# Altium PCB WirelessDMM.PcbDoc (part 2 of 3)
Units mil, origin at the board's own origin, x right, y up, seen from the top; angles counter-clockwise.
Board outline 6000 x 520 mil, 6 copper layers (Layer 1 - Top Layer, Layer 2 - GND, Layer 3 - Signal, Layer 4 - PWR, Layer 5 - GND, Layer 6 - Bottom Layer), stack 63.468 mil thick; 198 components, 117 nets, 636 pads, 272 vias.
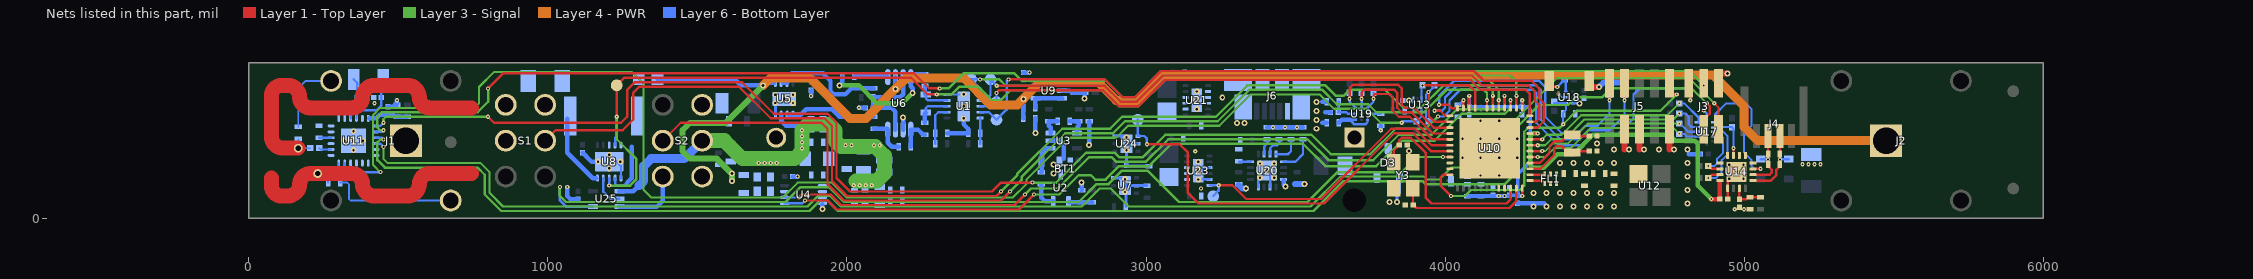
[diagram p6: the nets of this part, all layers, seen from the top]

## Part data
BT1: "HOLDER BATTERY AAA, TH"
C1: "CAP, CERM, 0.1 µF, 16 V, +/- 5%, X7R, 0402"
C2 C8 C9 C21 C25 C26 C29 C30 C31 C32 C33 C35 C38 C46 C51 C52 C71: "CAP, CERM, 0.1 µF, 10 V, +/- 10%, X5R, 0201"
C3 C4 C24 C28 C36 C47 C55 C58 C65 C66 C69 C72: "CAP, CERM, 1 µF, 10 V, +/- 10%, X5R, 0402"
C5 C27 C39 C68: "CAP, CERM, 1 µF, 6.3 V, +/- 20%, X5R, 0402"
C6: "CAP, CERM, 22 µF, 6.3 V, +/- 20%, X5R, 0402"
C7: "CAP, CERM, 4.7 µF, 35 V, +/- 10%, X5R, 0603"
C10 C11: "CAP, CERM, 1200 pF, 50 V, +/- 5%, C0G/NP0, 0402"
C12: "CAP, CERM, 0.1 µF, 50 V, +/- 5%, X7R, 0603"
C13: "CAP, CERM, 10 pF, 50 V, +/- 1%, C0G/NP0, 0603"
C14: "CAP, CERM, 0.01 µF, 100 V, +/- 1%, C0G/NP0, 0805"
C15: "CAP, CERM, 330 pF, 50 V, +/- 1%, C0G/NP0, 0402"
C16: "CAP, CERM, 470 pF, 50 V, +/- 1%, C0G/NP0, 0805"
C17: "CAP, CERM, 150 pF, 50 V, +/- 5%, C0G/NP0, 0402"
C18 C19: library part Capacitor, "Cap, 0402 footprint placeholder"
C20: "CAP, CERM, 2200 pF, 50 V, +/- 5%, C0G/NP0, 0603"
C22: "CAP, CERM, 100 pF, 100 V, +/- 1%, C0G/NP0, 0603"
C23: "CAP, CERM, 0.022 µF, 100 V, +/- 10%, X7R, 0603"
C34 C56 C57: "CAP, CERM, 4.7 µF, 10 V, +/- 10%, X5R, 0402"
C37 C49 C50: "CAP, CERM, 39 pF, 50 V, +/- 5%, C0G/NP0, 0402"
C40 C41: "CAP, CERM, 22 pF, 25 V, +/- 5%, C0G/NP0, AEC-Q200 Grade 1, 0201"
C42 C43 C44 C45: "CAP, CERM, 12 pF, 50 V, +/- 5%, C0G/NP0, 0201"
C48 C53: "CAP, CERM, 0.47 µF, 6.3 V, +/- 10%, X5R, 0201"
C54: "CAP, CERM, 2.2 µF, 16 V, +/- 10%, X5R, 0402"
C59 C62 C64 C67: "CAP, CERM, 10 µF, 10 V, +/- 20%, X5R, 0402"
C63: "CAP, CERM, 100 µF, 10 V, +/- 20%, X5R, 1206_190"
C70: "CAP, CERM, 2.2 µF, 6.3 V, +/- 10%, X5R, 0402"
D1 D2: "Diode, Schottky, 35 V, 0.1 A, SOD-523F"
D3: "MOSFET, P-CH, -20 V, -3.7 A, SOT-23"
F1: "Fuse, Resettable, 0.2 A, 24 VDC, SMD"
FID1 FID2 FID3 FID4 FID5 FID6: "Fiducial mark.  There is nothing to buy or mount."
FL1: "Filter, BandPass, 2.45GHz, SMD"
J1: "MAH561 Connector, XELW-4, Red, THD"
J2: "MAH561 Connector, XELW-4, Black, THD"
J3: "Header, 1.27 mm, 3x2, Au, SMT"
J4: "CONN FFC BOTTOM 4POS 1.00MM R/A"
J5: "Header, 1.27mm, 5x2, Gold, SMT"
J6: "Connector, Receptacle, Micro-USB Type B, R/A, Bottom Mount SMT"
L1 L2: "Inductor, Multilayer, Ferrite, 2.2 µH, 0.21 A, 0.15 ohm, SMD"
L3: "Ferrite Bead, 1500 ohm @ 100 MHz, 0.5 A, 0603"
Logo2: library part Pb-Free
Logo3: library part FCC_disclaimer, "FCC_disclaimer"
R1 R24: "RES, 13.3 k, 1%, 0.063 W, 0402"
R2: "RES, 8.2, 5%, 0.063 W, 0402"
R3: "RES, 10.0 k, 1%, 0.063 W, 0402"
R4 R14: "RES, 3.01 k, 1%, 0.063 W, 0402"
R5 R15: "RES, 52.3, 1%, 0.063 W, 0402"
R6: "RES, 9.76 k, 1%, 0.063 W, 0402"
R7: "RES, 100 k, 0.1%, 0.063 W, 0402"
R8: "RES, 1.00 M, 1%, 0.063 W, 0402"
R9: "RES, 100 M, 5%, 0.1 W, 0603"
R10: "RES, 10.0, 1%, 0.063 W, 0402"
R11 R13 R28 R29 R30 R31 R32 R51 R52 R53 R54 R56 R57 R58: "RES, 0, 5%, 0.063 W, 0402"
R12: "RES, 10.2 k, 1%, 0.063 W, 0402"
R16: "RES, 10.0 M, 1%, 0.3 W, 1206"
R17: "RES, 499 k, 1%, 0.063 W, 0402"
R19 R23: "RES, 133 k, 1%, 0.063 W, 0402"
R20: "RES, 95.3, 1%, 1 W, 2512"
R21: "RES, 11.3 k, 1%, 0.063 W, 0402"
R25: "RES, 0.5, 1%, 0.1 W, 0603"
R26 R27: "RES, 909, 1%, 0.05 W, 0201"
R33 R35 R36 R37 R38 R59 R60 R61 R62 R63 R64: "RES, 47.0 k, 1%, 0.05 W, AEC-Q200 Grade 0, 0201"
R34: "RES, 200 k, 1%, 0.063 W, 0402"
R39: "RES, 100 k, 1%, 0.05 W, 0201"
R40: "RES, 1.00 k, 1%, 0.05 W, 0201"
R41 R42 R43: "RES, 10.0 k, 1%, 0.05 W, 0201"
R44: "RES, 10.0 k, 1%, 0.1 W, 0402"
R45: "RES, 0.01, 1%, 0.25 W, 0805"
R46: "RES, 10 k, 5%, 0.063 W, 0402"
R47: "RES, 1.15 k, 1%, 0.063 W, 0402"
R48: "RES, 9.31 k, 1%, 0.063 W, 0402"
R49: "RES, 5.76 k, 1%, 0.063 W, 0402"
R50: "RES, 30.1 k, 1%, 0.063 W, 0402"
R55: "RES, 1.0 k, 5%, 0.063 W, 0402"
R65: library part RK73H1HTTC4702F, "RES, 47.0 k, 1%, 0.05 W, AEC-Q200 Grade 0, 0201"
S1 S2: "Switch, Slide, DPDT, On-On, 0.5 A, 125 V, TH"
S3: "SWITCH TACTILE SPST-NO 0.05A 12V"
TP1 TP2 TP3 TP4 TP6 TP9 TP10: library part TP_SM_1MM, "1mm Test Point, SMT"
TP7 TP8: library part TP_H0.45P0.75, "Testpoint"
U1: "18-Bit, 400-kSPS, Serial Interface, microPower, Miniature, True-Differential Input, SAR Analog-to-Digital Converter, DRC0010D"
U2: "30 ppm / degC Drift, 3.9 uA Voltage Reference, -40 to 125 degC, 3-pin SC70 (DCK), Green (RoHS & no Sb/Br)"
U3: "1-MHz, Micro-Power, Low-Noise, RRIO,1.8-V CMOS OPERATIONAL AMPLIFIER Precision Value Line Series, DCK0005A"
U4: "1-Ohm SP3T ANALOG SWITCH 5-V/3.3-V SINGLE-CHANNEL 3:1 MULTIPLEXER/DEMULTIPLEXER, DCU0008A"
U5: "1-MHz, Micro-Power, Low-Noise, RRIO,1.8-V CMOS OPERATIONAL AMPLIFIER Precision Value Line Series, DRG0008A"
U6: "Ultra Low Power, Rail-to-Rail Output, Fully-Differential Amplifier, DGK0008A"
U7: "Single Output LDO, 150 mA, Fixed 3 V Output, 2.2 to 5.5 V Input, with 0.5 uA Quiescent Current, 6-pin SON (DRV), -40 to 125 degC, Green (RoHS & no Sb/Br)"
U8: "0.3-ohm 2-Channel SPDT Bidirectional Analog Switch Dual-Channel 2:1 Multiplexer and Demultiplexer, DRC0010J"
U9: "17 uA, MicroPower, Precision, Zero Drift CMOS Operational Amplifier, 1.8 to 5.5 V, -40 to 125 degC, 5-pin SOT23 (DCK0005A), Green (RoHS & no Sb/Br)"
U10: "Ultra low-power ARM Cortex M3 2.4 GHz Radio MCU, Bluetooth Low Energy, RGZ0048A"
U11: "Mixed-Signal Microcontrollers, RGE0024G"
U12: "2.4GHz Antenna, 50 Ohms, SMD"
U13: "2-Channel Bidirectional Multi-Voltage Level Translator for Open-Drain & Push-Pull Application, DQE0008A"
U14: "DYNAMIC NFC INTERFACE TRANSPONDER, RGT0016C"
U15 U16: "ESD in 0402 Package with 10 pF Capacitance and 6 V Breakdown, 1 Channel, -40 to +125 degC, 2-pin X2SON (DPY), Green (RoHS & no Sb/Br)"
U17: "4-Bits Bidirectional Multi-Voltage Level Translator for Open-Drain and PushPull Application, RUT0012A"
U18: "Low-Power, Push-Button Controllers With Configurable Delay, DRY0006A"
U19: "System-Side Impedance Track Fuel Gauge, YZF0009-C01"
U20: "USB Friendly 0.5 A Li+ Charger with Dynamic Power Management, 10.5 V OVP, 4.3 V, -40 to 85 degC, 16-pin QFN (RGT), Green (RoHS & no Sb/Br)"
U21 U23: "360nA IQ Step Down Converter for Low Power Applications, DSS0012A"
U24: "Single Output LDO, 150 mA, Fixed 2.7 V Output, 2.2 to 5.5 V Input, with 0.5 uA Quiescent Current, 6-pin SON (DRV), -40 to 85 degC, Green (RoHS & no Sb/Br)"
U25: "0.9-Ohm SPST ANALOG SWITCH, DCK0005A"
Y1: "Crystal, 32.768 KHz, 12.5 pF, SMD"
Y2: "Crystal, 32.768kHz, 12.5pF, SMD"
Y3: "Crystal, 24 MHz, 9 pF, SMD"
ZZ2 ZZ3 ZZ4: library part AssemblyNote

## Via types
v1: diameter 14, hole 6, Layer 1 - Top Layer to Layer 6 - Bottom Layer, tented both sides, 136 vias
v2: diameter 20, hole 10, Layer 1 - Top Layer to Layer 6 - Bottom Layer, tented both sides, 85 vias
v3: diameter 19.68, hole 7.87, Layer 1 - Top Layer to Layer 6 - Bottom Layer, tented both sides, 35 vias
v4: diameter 19.68, hole 7.87, Layer 1 - Top Layer to Layer 6 - Bottom Layer, 14 vias
v5: diameter 10, hole 6, Layer 1 - Top Layer to Layer 6 - Bottom Layer, tented both sides, 2 vias

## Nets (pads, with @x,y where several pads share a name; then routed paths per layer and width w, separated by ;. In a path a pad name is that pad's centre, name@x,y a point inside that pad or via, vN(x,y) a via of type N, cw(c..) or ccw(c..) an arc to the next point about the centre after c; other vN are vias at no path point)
ADS8881_CNVST: TP4.1 U1.6 U10.14 | length 2050.7
  Layer 1 - Top Layer w8: U10.14@4238.58,368.86 v1(4238.58,410)
  Layer 3 - Signal w8: v1(2445.12,464.88) 2510.12,464.88 2531,444 2861.79,444 2915.79,390 2968.79,390 3056.79,478 4217,478 4238.58,456.42 v1(4238.58,410)
  Layer 6 - Bottom Layer w8: U1.6@2445.12,414.37 2445.12,434.88 TP4.1@2415,465 2445,465 v1(2445.12,464.88)
ADS8881_MISO: TP3.1 U1.7 U10.11 | length 2136
  Layer 1 - Top Layer w8: v1(2501,444) 2861.79,444 2915.79,390 2968.79,390 3056.79,478 4090.79,478 4123.79,445 4280,445 4300,425 4300,395 4315,380 4315,335 4303.58,323.58 U10.11@4283.86,323.58
  Layer 6 - Bottom Layer w8: U1.7@2445.12,394.68 2461.68,394.68 2480,413 TP3.1@2480,465 v1(2501,444)
ADS8881_MOSI: TP1.1 U1.9 U10.10 | length 2248.4
  Layer 1 - Top Layer w8: v1(2540,465) 2862,465 2922,405 2962.57,405 3050.57,493 4097,493 4130,460 4290,460 4315,435 4315,401.21 4330,386.21 4330,325 4308.9,303.9 U10.10@4283.86,303.9
  Layer 6 - Bottom Layer w8: U1.9@2445.12,355.31 2474.68,355.31 TP1.1@2500,330 2534,364 2534,459 v1(2540,465)
ADS8881_SCLK: TP2.1 U1.8 U10.12 | length 2030.4
  Layer 1 - Top Layer w8: v1(2500,420) 2509,429 2855.57,429 2909.57,375 2975,375 3063,463 4084.57,463 4117.57,430 4270,430 4283.86,416.14 U10.12@4283.86,343.27
  Layer 6 - Bottom Layer w8: U1.8@2445.12,375 2484,375 2498,389 TP2.1@2500,389 v1(2500,420)
AFE_IRNG-SEL: TP6.1 U8.4 U8.8 U10.17 | length 3721
  Layer 1 - Top Layer w8: v1(1230,340) TP6.1@1230,445 1255,470 2215,470 2270,415 v1(2300,415) ; U10.17@4179.53,368.86 v1(4179.53,395)
  Layer 3 - Signal w8: v1(1205,110) 1275,110 1295,130 1295,200 1230,265 v1(1230,340) ; v1(2300,415) 2350,415 2375,440 2440,440 2484,396 2515,396 2548,429 2855.57,429 2909.57,375 2975,375 3063,463 4147,463 4179.53,430.47 v1(4179.53,395)
  Layer 6 - Bottom Layer w8: v1(1205,110) U8.8@1205,134.88 ; U8.4@1224.68,245.12 1224.68,269.68 1230,275 v1(1230,340)
AFE_RIN-SEL: S2.5 U10.19 | length 3273.5
  Layer 1 - Top Layer w8: S2.5@1384.06,260 1444.06,320 1915,320 1935,300 1935,115 1990,60 2515,60 v1(2545,90) ; U10.19@4140.16,368.86 v1(4140.16,395)
  Layer 3 - Signal w8: v1(2545,90) 2585,130 2585,140 2730,285 2890,285 2930,325 3240,325 3345,430 3590,430 3638,382 3743,382 3770,355 3930,355 4005,430 4130,430 4140.16,419.84 v1(4140.16,395)
AFE_VI-SEL: S1.2 U10.18 | length 3855.1
  Layer 1 - Top Layer w8: S1.2@990.94,260 1025.94,295 1250,295 1285,330 1285,420 1305,440 1640,440 1745,335 1925,335 1950,310 1950,125 2000,75 2500,75 v1(2515,90) ; U10.18@4159.84,368.86 v1(4159.84,410)
  Layer 3 - Signal w8: v1(2515,90) 2570,145 2570,150 2720,300 2880,300 2920,340 3233.79,340 3338.79,445 3600,445 3635,410 3660,410 3680,430 3800,430 3860,370 3920,370 3995,445 4140,445 4159.84,425.16 v1(4159.84,410)
AFE_VRNG-SEL0: U4.6 U10.16 | length 2709.5
  Layer 1 - Top Layer w8: v1(1840,70.16) 1849.84,80 1945,80 1980,45 2560,45 v1(2595,80) ; U10.16@4199.21,368.86 v1(4199.21,410)
  Layer 3 - Signal w8: v1(2595,80) 2615,100 2705,100 2810,205 2885,205 2900,190 3000,190 3075,265 3540,265 3610,195 3760,195 3845,280 3955,280 4040,365 4190,365 4199.21,374.21 v1(4199.21,410)
  Layer 6 - Bottom Layer w8: U4.6@1792.01,70.16 v1(1840,70.16)
AFE_VRNG-SEL1: U4.5 U10.15 | length 2710.5
  Layer 1 - Top Layer w8: v1(1860,60) 1935,60 1965,30 2575,30 v1(2625,80) ; U10.15@4218.9,368.86 v1(4218.9,395)
  Layer 3 - Signal w8: v1(2625,80) 2710,80 2775,145 2815,145 2830.1,129.9 2864.9,129.9 2910,175 3010,175 3085,250 3525,250 3600,175 3770,175 3855,260 3965,260 4055,350 4200,350 4218.9,368.9 v1(4218.9,395)
  Layer 6 - Bottom Layer w8: U4.5@1792.01,50.47 1850.47,50.47 v1(1860,60)
AINM: C20.1 R15.2 U1.4 | length 118.7
  Layer 6 - Bottom Layer w8: R15.2@2260,442 R15.2@2261,443 ; C20.1@2265,415 2265,400 2270.32,394.68 U1.4@2334.88,394.68
  Layer 6 - Bottom Layer w15: R15.2@2261,443 2261,417 C20.1@2264,414
AINP: C20.2 R5.2 U1.3 | length 124
  Layer 6 - Bottom Layer w8: C20.2@2264,354 2264,369 2270,375 U1.3@2334.88,375
  Layer 6 - Bottom Layer w15: R5.2@2260,320 2260,350 C20.2@2264,354
BQ27426_GPIO: R43.1 U10.29 U19.A1 | length 416.1
  Layer 1 - Top Layer w8: v1(3760.85,400) 3760.85,410.85 3766,416 3814,416 3825,405 3825,360 3845,340 3882,340 3957.47,264.53 U10.29@4016.14,264.53
  Layer 6 - Bottom Layer w8: U19.A1@3740.53,369.69 3760.85,390 R43.1@3760.85,420.04
BQ27426_SCL: R41.1 U10.27 U19.A3 | length 526
  Layer 1 - Top Layer w8: v1(3680.85,400) 3680.85,435.85 3692,447 3843,447 3855,435 3855,380 3865,370 3896,370 3962.1,303.9 U10.27@4016.14,303.9
  Layer 6 - Bottom Layer w8: R41.1@3680.85,420.04 3680.85,390 U19.A3@3701.16,369.69
BQ27426_SDA: R42.1 U10.28 U19.A2 | length 461.4
  Layer 1 - Top Layer w8: v1(3720.85,400) 3720.85,421.85 3730,431 3829,431 3840,420 3840,370 3855,355 3888,355 3958.79,284.21 U10.28@4016.14,284.21
  Layer 6 - Bottom Layer w8: U19.A2@3720.85,369.69 v1(3720.85,400) R42.1@3720.85,420.04
CAP02: R26.1 R28.2 TP7.1 | length 908.4
  Layer 1 - Top Layer w50: 75,135 75,110 ccw(c110,110) 110,75 130,75 ccw(c130,115) 170,115 cw(c205,115) 205,150 TP7.1@230,150 345,150 cw(c345,115) 380,115 ccw(c420,115) 420,75 530,75 ccw(c530,115) 570,115 cw(c605,115) 605,150 745,150
  Layer 6 - Bottom Layer w6: TP7.1@230,150 R26.1@270.04,150 ; R28.2@265,120 R26.1@265,144.96
CAP12: R27.1 R31.2 TP8.1 | length 1136.3
  Layer 1 - Top Layer w50: TP8.1@165,235 115,235 cw(c115,275) 75,275 75,410 cw(c110,410) 110,445 130,445 cw(c130,405) 170,405 ccw(c205,405) 205,370 345,370 ccw(c345,405) 380,405 cw(c420,405) 420,445 530,445 cw(c530,405) 570,405 ccw(c605,405) 605,370 745,370
  Layer 6 - Bottom Layer w6: R31.2@165,265 TP8.1@165,235 R27.1@205.04,235
CC2640_HFXN: C45.1 U10.46 Y3.3 | length 678.6
  Layer 1 - Top Layer w8: Y3.3@3828.5,188.31 3828.5,226.5 C45.1@3847.01,245 3847.01,262.01 3855,270 3885,270 3935,220 3935,70 3955,50 4205,50 4218.9,63.9 U10.46@4218.9,101.14
CC2640_HFXP: C44.1 U10.47 Y3.1 | length 460.2
  Layer 1 - Top Layer w8: Y3.1@3896.48,101.69 3892.99,98.21 C44.1@3892.99,45 3895,45 3905,35 4215,35 4238.58,58.58 U10.47@4238.58,101.14
CC2640_NRESET: C70.1 J5.10 R40.1 U10.35 U18.1 | length 1246.7
  Layer 1 - Top Layer w8: U10.35@4016.14,146.42 3993.58,146.42 3985,137.83 3985,110 v1(4020,75) ; J5.10@4755,415 v1(4775,415)
  Layer 3 - Signal w8: v1(4020,75) 4066.81,75 4086.81,95 4250,95 4265,110 4265,290 4278.9,303.9 4383.9,303.9 v1(4395,315) 4440,360 4720,360 v1(4775,415)
  Layer 6 - Bottom Layer w7: R40.1@4365,385.04 4365.28,385.31 U18.1@4404.17,385.31 4404.17,362.17 4395,353 C70.1@4395,350 v1(4395,315)
CC2650_LFXI: C42.2 U10.4 Y2.2 | length 252.3
  Layer 1 - Top Layer w8: U10.4@4283.86,185.79 4316.79,185.79 4349.44,218.44 4349.44,241.44 4365.56,257.56 4389.56,257.56 4411.53,279.53 Y2.2@4425,279.53 4429.53,275 C42.2@4482.01,275
CC2650_LFXO: C43.1 U10.3 Y2.1 | length 253.9
  Layer 1 - Top Layer w8: U10.3@4283.86,166.1 4319.1,166.1 4365,212 4365,235 4372,242 4389,242 4410.53,220.47 Y2.1@4425,220.47 4429.53,225 C43.1@4482.01,225
COM: C18.2 C19.2 C27.1 J2.1 R9.2 R25.1 R55.1 U4.7 U5.5 U6.2 | length 5267.7
  Layer 3 - Signal w20: v2(1615,125) v2(1615,150) 1565,200 1475,200 1450,225 1450,295 1475,320 1595,320 v2(1720,445)
  Layer 4 - PWR w30: v2(1720,445) 1745,470 1875,470 2010,335 2064.2,335 v2(2162.2,433) 2199.2,470 2390,470 2480,380 2570,380 v2(2590,400) 2645,455 2840,455 2900,395 2970,395 3055,480 4895,480 5000,375 5000,305 5045,260 J2.1@5474.61,260
  Layer 6 - Bottom Layer w15: R25.1@1366.5,465 1625,465 1645,445 v2(1720,445) 1728.15,453.15 U5.5@1757.15,453.15 ; v2(2162.2,433) U6.2@2162.2,472.6 ; C27.1@2590,334.7 R55.1@2590,370 v2(2590,400)
CURR_IN: F1.1 S1.4
DMM_IN: J1.1 S1.5
GND: BT1.2 C2.1 C3.1 C4.1 C5.2 C6.2 C7.2 C8.1 C9.1 C21.1 C24.2 C25.1 C26.1 C27.2 C28.2 C29.2 C30.2 C31.2 C32.2 C33.2 C34.2 C35.2 C36.2 C37.2 C38.1 C39.2 C40.2 C41.2 C42.1 C43.2 C44.2 C45.2 C46.2 C47.2 C48.2 C51.1 C52.2 C53.2 C54.2 C55.1 C56.2 C57.2 C58.2 C59.2 C62.2 C63.2 C64.2 C65.2 C66.2 C67.2 C68.2 C69.2 C70.2 C71.1 C72.2 D3.1 FL1.2 FL1.5 FL1.6 J3.6 J5.3 J5.5 J5.9 J6.5 J6.6 J6.7 J6.8 J6.9 J6.10 J6.11 R24.1 R29.1 R44.2 R46.1 R47.1 R48.1 R49.1 R50.1 S1.1 S2.6 S3.1 U1.5 U1.11 U2.3 U3.2 U4.4 U5.4 U5.9 U6.6 U7.3 U7.5 U7.7@2930,110 U8.6 U8.11 U9.2 U10.33 U10.34 U10.49 U11.5 U11.6 U11.7 U11.8 U11.9 U11.10 U11.13 U11.15 U11.17 U11.18 U11.19 U11.20 U11.23 U11.25 U13.1 U14.4 U14.5 U14.6 U14.8 U14.9 U14.13 U14.17@4974.47,156.09 U15.2 U16.2 U17.6 U18.2 U18.6 U19.B2 U20.4 U20.6 U20.8 U20.17@3405,160 U21.3 U21.4 U21.8 U21.9 U21.10 U21.13@3170,395 U23.3 U23.4 U23.9 U23.11 U23.13@3175,160 U24.3 U24.5 U24.7@2935,250 U25.3 Y3.2 Y3.4 | length 2786.8
  Layer 1 - Top Layer w8: C48.2@4944.99,65 4944.99,124.99 U14.17@4974.47,154.47
  Layer 1 - Top Layer w20: S3.1@4481.93,460 4486.93,455 4486.93,440 v2(4515,440) ; 4600,230 J5.3@4600,298.23 ; 4650,230 J5.5@4650,298.23 ; 4750,230 J5.9@4750,298.23 ; J3.6@4920,485 v2(4945,485)
  Layer 6 - Bottom Layer w6: v1(4379,417) 4391,405 U18.2@4403.19,405
  Layer 6 - Bottom Layer w7: U18.6@4426.81,385.31 4449.69,385.31 v2(4450,385) ; v1(4865,361) 4875,351 U17.6@4875,323.46
  Layer 6 - Bottom Layer w8: U8.11@1225,195 1244.37,175.63 U8.6@1244.37,134.88 ; U1.5@2334.88,414.37 2388.03,414.37 U1.11@2390,412.4 ; U23.13@3175.26,130.47 U23.11@3212.4,130.47 U23.11@3212.66,130.47 ; U23.13@3175.26,160 3185.1,169.84 U23.9@3212.4,169.84 U23.9@3212.66,169.84 ; U20.8@3375.47,104.88 3375.47,130.47 v3(3381.38,136.38) v3(3405,160) 3414.84,150.16 U20.6@3414.84,104.88
  Layer 6 - Bottom Layer w10: U5.4@1760.47,346.85 v4(1760.47,386.22) ; U7.3@2891.61,135.59 U7.7@2919.41,135.59 ; U24.3@2896.61,275.59 U24.7@2934.41,275.59 ; v4(2930,88.35) 2933,85.35 C24.2@2933,40 ; U7.7@2930,110 U7.5@2968.39,110 C72.2@3003,110 ; C65.2@2934.74,180 U24.7@2934.74,228.09 ; U24.7@2935,250 U24.5@2973.39,250 ; C65.2@2939.74,175 C66.2@3010,175 ; v2(3840,55) 3840,78 3847.4,85.4 D3.1@3847.4,138.76
  Layer 6 - Bottom Layer w15: C35.2@465,372.99 482.99,372.99 490,380 C34.2@495,380 v1(495,395) ; v1(1065,105) 1065,75 1074.99,65.01 C71.1@1101,65.01 ; C26.1@1116,220.01 1146.01,190 v4(1167.6,190) ; U25.3@1239.29,39.72 1364.72,39.72 1384.06,59.06 S2.6@1384.06,139.92 ; C8.1@1817.99,140 v1(1835,140) ; v1(1879.99,409.01) C21.1@1880,429.01 ; v2(1917.99,32.01) U4.4@1917.99,48 ; v1(2040,370) C9.1@2062.01,370 ; U6.6@2187.8,297.4 v2(2187.8,337) ; C3.1@2335,285 C4.1@2405,285 2405,300 2390,315 U1.11@2390,337.6 ; C25.1@2590,487.99 v1(2610,487.99) ; v2(2630,285) C27.2@2630,334.7 ; U3.2@2680.71,260 2710,260 2725,245 2725,200 ; U9.2@2719.29,427.22 2745.78,427.22 2753,420 C68.2@2760,420 R24.1@2795,420 v2(2795,401) ; C5.2@2785,95 v2(2785,120) ; v2(2810,245) C6.2@2810,325 ; R50.1@3405,305 v1(3425,305) R47.1@3445,305 v1(3465,305) R49.1@3485,305 v1(3505,305) R46.1@3525,305 ; U20.4@3460.12,127 3460.12,112.88 v2(3466,107) ; 3590,320 C58.2@3605,320 ; 3590,390 C54.2@3605,390 ; 3600,355 C53.2@3617.01,355 ; v1(3785,295) R44.2@3785,310 ; C32.2@4243,51.01 4330.99,51.01 ; 4815,215 C51.1@4854.01,215
  Layer 6 - Bottom Layer w20: C56.2@3310,112 3322,100 v2(3335,100) ; C57.2@3499,115 C57.2@3505,115 v2(3530,115) ; v2(4515,440) 4529.69,454.69 U16.2@4600,454.69
  other v1: 4968.94,31.09 5000,31.09 3184,100 5195,181.3 5215,181.3 5235,181.3 5255,181.3 3165,225 420,385
  other v2: 4295,40 4340,40 4385,40 4430,40 4475,40 4520,40 4565,40 4810,50 3815,55 4295,85 4340,85 4385,85 4430,85 4475,85 4520,85 4565,85 4810,95 4810,140 2690,150 2690,180 4385,185 4430,185 4475,185 4520,185 4565,185 4810,185 3880,226 4565,230 4615,230 4665,230 4715,230 4765,230 4810,230 4508,250 3570,300 3305,320 3330,320 3570,330 3570,360 3570,390 3879,395 3255,405
  other v3: 3175,130.47 4950.85,132.47 4998.09,132.47 3428.62,136.38 4118.37,143.46 4181.63,143.46 4974.47,156.09 3175,160 4950.85,179.71 4998.09,179.71 3381.38,183.62 3428.62,183.62 3175,189.53 4058.46,203.37 4118.37,203.37 4181.63,203.37 4241.54,203.37 2935,228.35 350,228.5 318.5,260 350,260 381.5,260 4058.46,266.63 4118.37,266.63 4181.63,266.63 4241.54,266.63 2935,271.65 350,291.5 4118.37,326.54 4181.63,326.54 3170,365.47 3170,395 3170,424.53
  other v4: 2930,131.65 1205,167.36 1242.4,190 1205,212.64 2390,334.65 2390,375 1819.53,386.22 1790,400 1760.47,413.78 1819.53,413.78 2390,415.35
  other v5: 3720.85,350
I-SEL: U10.32 U25.4 | length 3369.3
  Layer 1 - Top Layer w8: v1(3993,205.47) U10.32@4016.14,205.47
  Layer 3 - Signal w8: v1(1040,105) 1040,75 1060,55 1795,55 1845,105 1940,105 1990,55 2775,55 2835,115 2875,115 2920,160 3005,160 3110,55 3540,55 3640,155 3855,155 3905.47,205.47 v1(3993,205.47)
  Layer 6 - Bottom Layer w8: v1(1040,105) 1040,60 1060.28,39.72 U25.4@1150.71,39.72
IN_P: C10.1 C11.1 C12.1 C13.1 C14.1 C15.1 C16.1 C17.1 C18.1 C19.1 R10.1 R11.1 R12.1 R13.1 S2.2 U5.3 U25.1 | length 1431.5
  Layer 3 - Signal w50: S2.2@1515.94,260 1590,260 1650,200 1825,200 1850,225 v1(1850,235) v1(1850,255) v1(1850,275) v1(1850,295) 1870,315 1940,315 1960,295 1960,260 1980,240 2095,240 2125,210 2125,150 2100,125 2030,125
  Layer 6 - Bottom Layer w15: U25.1@1239.29,90.91 1285.91,90.91 1305,110 ; U5.3@1780.16,346.85 1780.16,325.84 1796,310 1835,310 v1(1850,295)
  Layer 6 - Bottom Layer w30: 1305,110 1320,125 1320,175 1345,200 1455.94,200 S2.2@1515.94,260
  other v1: 2023,111 2043,111 2063,111 2083,111 1705,185 1725,185 1745,185 1765,185 1995,245 2015,245 2090,245 2110,245
JTAG_TCK: J5.4 U10.25 U16.1 | length 1042.1
  Layer 1 - Top Layer w8: v1(3965,360) 3984,360 4000.73,343.27 U10.25@4016.14,343.27 ; v1(4600,395) J5.4@4600,451.77
  Layer 6 - Bottom Layer w8: v1(3965,360) 3990,360 4000,370 4000,405 4040,445 4305,445 4320,430 4320,330 4385,265 4450,265 4480,295 4550,295 4600,345 v1(4600,395) U16.1@4600,415.32
JTAG_TMS: J5.2 U10.24 U15.1 | length 967.1
  Layer 1 - Top Layer w8: v1(3980,380) 4010.59,380 4021.73,368.86 U10.24@4041.73,368.86 ; v1(4550,395) J5.2@4550,451.77
  Layer 6 - Bottom Layer w8: v1(3980,380) 3980,410 4030,460 4315,460 4335,440 4335,340 4390,285 4445,285 4470,310 4510,310 4550,350 v1(4550,395) U15.1@4550,415.32
MSP430_1P4-UCATX: J3.3 U11.3 | length 5080.4
  Layer 1 - Top Layer w8: J3.3@4865,298.23 4865,330 4885,350 4885,375 v1(4875,385)
  Layer 3 - Signal w8: v1(450,264.37) 439.37,264.37 430,255 430,195 455,170 765,170 788.79,146.21 788.79,80 843.79,25 1875,25 1910,60 1935,60 1970,25 3560,25 3660,125 3925,125 3935,115 4200,115 4220,135 4220,285 4314.5,379.5 4411.5,379.5 4437,405 4525,405 4555,435 4825,435 v1(4875,385)
  Layer 6 - Bottom Layer w8: U11.3@424.8,269.84 444.53,269.84 v1(450,264.37)
MSP430_1P5-UCARX: J3.5 U11.4 | length 5075.3
  Layer 1 - Top Layer w7: v1(4900,385) 4915,370 J3.5@4915,298.23
  Layer 3 - Signal w7: v1(450,239.37) 450,200 465,185 775,185 805,155 805,85 850,40 1868,40 1903,75 1945,75 1980,40 2785,40 2845,100 2882.36,100 2942.36,40 3550,40 3650,140 3930,140 3940,130 3980,130 4020,170 4135,170 4150,185 4150,280 4165,295 4200,295 4375,470 4815,470 v1(4900,385)
  Layer 6 - Bottom Layer w8: U11.4@424.8,250.16 439.21,250.16 v1(450,239.37)
MSP430_2P3: R61.1 U11.11 U13.6 | length 4594.5
  Layer 3 - Signal w7: v1(440,155) 415,180 415,345 440,370 755,370 769.76,384.76 769.76,439.76 820,490 1280,490 1320,450 1320,95 1345,70 1785,70 1835,120 1950,120 2000,70 2555,70 2600,115 2600,130 2740,270 2900,270 2940,310 3245,310 3350,415 3580,415 3628,367 3738,367 3785,320 v1(3855,320)
  Layer 6 - Bottom Layer w7: v1(3855,320) 3859.96,324.96 R61.1@3905,324.96 3921.89,341.85 U13.6@3921.89,362.28 U13.6@3921.89,371
  Layer 6 - Bottom Layer w8: U11.11@320.47,185.2 320.47,167.53 333,155 v1(440,155)
MSP430_2P3-V1P9: R59.1 U10.21 U13.3 | length 297.1
  Layer 1 - Top Layer w8: v1(3925,445.04) 4080,445 4100.79,424.21 U10.21@4100.79,368.86
  Layer 6 - Bottom Layer w7: U13.3@3921.89,389 U13.3@3921.89,397.72 3921.89,441.93 v1(3925,445.04)
MSP430_NRES/TDIO: J3.2 R60.2 U11.1 U13.5 | length 5449.6
  Layer 1 - Top Layer w8: v1(800,340) 820,320 1245,320 1265,340 1265,430 1290,455 1650,455 1755,350 1935,350 1965,320 1965,135 2010,90 2485,90 2515,120 v1(2620,120) ; J3.2@4815,451.77 4820,446.77 v1(4820,395)
  Layer 3 - Signal w8: v1(450,320) 450,332 458,340 v1(800,340) ; v1(2620,120) 2700,120 2800,220 2895,220 2910,205 2990,205 3065,280 3553,280 3618,215 3750,215 3835,300 3935,300 v1(3976,341)
  Layer 6 - Bottom Layer w7: U13.5@3935.67,362.28 3935.67,336.33 R60.2@3945,327
  Layer 6 - Bottom Layer w8: U11.1@424.8,309.21 439.21,309.21 v1(450,320) ; R60.2@3945,324.96 3959.96,324.96 v1(3976,341) 3996,341 4015,360 4015,395 4050,430 4295,430 4305,420 4305,320 4380,245 4455,245 4490,280 4575,280 4630,335 4630,415 4650,435 4810,435 4820,425 v1(4820,395)
MSP430_NRES/TDIO-V1P9: R33.1 U10.26 U13.4 | length 227.4
  Layer 1 - Top Layer w8: v1(3945,423) 3945,343 3964.42,323.58 U10.26@4016.14,323.58
  Layer 6 - Bottom Layer w7: U13.4@3935.67,389 U13.4@3935.67,397.72 3935.67,413.67 v1(3945,423) 3965,443 R33.1@3965,445.04
MSP430_TST/TCK: J3.4 U11.2 | length 4746.3
  Layer 1 - Top Layer w8: v1(800,435) 850,485 2225,485 2275,435 v1(2310,435) ; v1(4865,445) J3.4@4865,451.77
  Layer 3 - Signal w8: v1(450,295) 439,295 430,304 430,340 445,355 765,355 800,390 v1(800,435) ; v1(2310,435) 2340,435 2390,485 2560,485 2585,460 2867,460 2922,405 2962.57,405 3050.57,493 4817,493 v1(4865,445)
  Layer 6 - Bottom Layer w8: U11.2@424.8,289.53 444.53,289.53 v1(450,295)
MSP430XIN: C40.1 U11.22 Y1.1 | length 202.4
  Layer 6 - Bottom Layer w8: U11.22@359.84,334.8 359.84,354.84 367,362 427,362 443,378 C40.1@443,405 443,458.78 Y1.1@449.22,465
MSP430XOUT: C41.1 U11.21 Y1.2 | length 143.9
  Layer 6 - Bottom Layer w8: U11.21@340.16,334.8 340.16,365.16 362.02,387.02 C41.1@362.02,405 362.02,453.78 Y1.2@350.8,465
NetBT1_1: BT1.1 D3.3
NetC1_1: C1.1 R1.1 U3.3 | length 71.8
  Layer 6 - Bottom Layer w15: U3.3@2680.71,285.59 2680.71,304.29 2675,310 R1.1@2675,325 C1.1@2705,325
NetC1_2: C1.2 R2.1 U3.4 | length 71.8
  Layer 6 - Bottom Layer w15: C1.2@2745,325 R2.1@2775,325 2775,310 2769.29,304.29 U3.4@2769.29,285.59
NetC3_2: C3.2 R52.1 U1.2 | length 139.2
  Layer 6 - Bottom Layer w8: R52.1@2295,250 C3.2@2295,285 2295,345 2305.31,355.31 U1.2@2334.88,355.31
NetC4_2: C4.2 R51.1 U1.10 | length 85.7
  Layer 6 - Bottom Layer w8: R51.1@2445,250 2445.12,250.12 U1.10@2445.12,335.63
NetC5_1: C5.1 R53.1 U2.1 | length 76.7
  Layer 6 - Bottom Layer w15: U2.1@2743.3,55 C5.1@2785,55 R53.1@2820,55
NetC7_1: C7.1 R3.2 U3.1 | length 98.7
  Layer 6 - Bottom Layer w15: R3.2@2650,155 2651,156 C7.1@2651,190 2651,216 2669.41,234.41 U3.1@2680.71,234.41
NetC9_2: C9.2 R54.1 U6.3 U6.7 | length 335.1
  Layer 6 - Bottom Layer w15: U6.7@2162.2,297.4 2162.2,356.8 2149,370 C9.2@2087.99,370 R54.1@2088,405 2177,405 2187.8,415.8 U6.3@2187.8,472.6
NetC10_2: C10.2 C11.2 C12.2 R6.2 U4.3
NetC13_2: C13.2 C14.2 R7.2 U4.2
NetC15_2: C15.2 C16.2 C17.2 R8.2 U4.1
NetC22_2: C22.2 R16.2 S2.1
NetC23_1: C23.1 R17.1 S2.3
NetC28_1: C28.1 C29.1 C30.1 C31.1 C32.1 C33.1 R56.1 U10.13 U10.22 U10.44 U10.45 U10.48 | length 850.6
  Layer 1 - Top Layer w8: U10.22@4081.1,368.86 v1(4081.1,410) ; v1(4258.27,75) U10.48@4258.27,101.14 ; U10.13@4258.27,368.86 v1(4258.27,395)
  Layer 6 - Bottom Layer w12: R56.1@4075,75 C28.1@4120,75 4157.99,75 C33.1@4160,77.01 4162.01,75 v1(4179.53,75) v1(4199.21,75) C31.1@4215,75 ; v1(4081.1,410) 4081,409.9 C30.1@4081,372.99 4081.35,373.35 C29.1@4258,373.35 ; C31.1@4215,77.01 C32.1@4243,76.99 ; v1@4258,394.73 C29.1@4258,373.35 ; v1(4258.27,75) 4244.99,75 C32.1@4243,76.99 ; C32.1@4243,76.99 4243,148 4285,190 4285,365 4276.65,373.35 C29.1@4258,373.35
NetC34_1: C34.1 C35.1 R57.1 U11.24 | length 135
  Layer 6 - Bottom Layer w15: U11.24@403,334.8 425.8,334.8 438.01,347.01 C35.1@465,347.01 482.99,347.01 490,340 C34.1@495,340 R57.1@530,340
NetC36_1: C36.1 U11.16 | length 40.3
  Layer 6 - Bottom Layer w8: C36.1@235,270 235.16,269.84 U11.16@275.2,269.84
NetC37_1: C37.1 R30.1 U12.1
NetC39_1: C39.1 U10.23 | length 50.8
  Layer 1 - Top Layer w8: U10.23@4061.42,368.86 v1(4061.42,395)
  Layer 6 - Bottom Layer w8: C39.1@4043,380 4046.42,380 v1(4061.42,395)
NetC46_1: C46.1 C47.1 R58.1 U14.15 | length 109.9
  Layer 1 - Top Layer w8: U14.15@4984.31,100.97 4984.31,64.24 C46.1@4984.47,64.08 5008.08,64.08 5015.09,71.09 C47.1@5019.47,71.09 R58.1@5054.47,71.09
NetC53_1: C53.1 C54.1 U19.B3 | length 96.1
  Layer 6 - Bottom Layer w8: C54.1@3645,390 3645,357.01 C53.1@3642.99,355 3670,355 3675,350 U19.B3@3701.16,350
NetC58_1: C58.1 D3.2 R45.1 U19.C1 U19.C3 | length 138.5
  Layer 6 - Bottom Layer w8: 3680,330.32 3695,315.32 3734.31,315.32 3740.53,321.53 U19.C1@3740.53,330.32 ; 3690.32,330.32 U19.C3@3701.16,330.32
  Layer 6 - Bottom Layer w15: C58.1@3645,320 3655.32,330.32 3680,330.32 3690.32,330.32
NetC68_1: C68.1 R21.1 R24.2 U9.1 | length 113.7
  Layer 6 - Bottom Layer w8: C68.1@2755,460 C68.1@2760,460
  Layer 6 - Bottom Layer w15: U9.1@2719.29,452.81 2747.81,452.81 C68.1@2755,460 ; C68.1@2760,460 R24.2@2795,460 R21.1@2830,460
NetC69_1: C69.1 L3.2 R56.2
NetF1_2: F1.2 R20.2 U8.3 U8.10 | length 245.5
  Layer 6 - Bottom Layer w15: R20.2@1065,333.2 1065,220 1150.12,134.88 U8.10@1162,134.88
NetFL1_1: FL1.1 R32.2
NetFL1_3: FL1.3 U10.2 | length 50.6
  Layer 1 - Top Layer w8: U10.2@4283.86,146.42 4330.49,146.42 FL1.3@4333.31,149.24
NetFL1_4: FL1.4 U10.1 | length 54.7
  Layer 1 - Top Layer w8: U10.1@4283.86,126.73 4325.27,126.73 4333.31,118.69 FL1.4@4333.31,116.76
NetJ1_2: J1.2 R28.1 | length 423.6
  Layer 6 - Bottom Layer w6: R28.1@305,120 329,120 335,114 335,65 340,60 J1.2@675,60
NetJ1_4: J1.4 R31.1 | length 250.4
  Layer 6 - Bottom Layer w6: R31.1@165,305 R31.1@165,306 165,435 190,460 J1.4@275,460
NetL1_1: L1.1 U21.2
NetL2_1: L2.1 U23.2
NetR3_1: R3.1 U2.2 | length 89.5
  Layer 6 - Bottom Layer w15: R3.1@2650,115 2650,70 2662.29,57.71 U2.2@2689.41,57.71
NetR4_1: R4.1 U5.1 U5.2 | length 308
  Layer 6 - Bottom Layer w15: U5.2@1804.32,346.85 U5.1@1824,346.85 ; U5.1@1819.53,346.85 1845.85,346.85 1864,365 1950,365 1975,340 R4.1@2090,340
NetR4_2: R4.2 R19.2 U6.8 | length 130.4
  Layer 6 - Bottom Layer w15: R4.2@2090,300 U6.8@2134.02,300 ; U6.8@2136.61,297.4 2136.61,253.39 2150,240 R19.2@2173.39,240
NetR5_1: R5.1 R19.1 U6.5 | length 111.2
  Layer 6 - Bottom Layer w15: R19.1@2213.39,240 U6.5@2213.39,297.4 2237.6,297.4 2255,280 R5.1@2260,280
NetR6_1: R6.1 R10.2
NetR7_1: R7.1 R11.2
NetR8_1: R8.1 R12.2
NetR9_1: R9.1 R13.2
NetR14_1: R14.1 R23.1 U6.1 | length 109.2
  Layer 6 - Bottom Layer w15: R23.1@2025,475 R14.1@2090,475 U6.1@2134.21,475
NetR14_2: R14.2 U5.6 U5.7 | length 385
  Layer 6 - Bottom Layer w15: 1785.15,453.15 U5.7@1799.84,453.15 1799.84,468.84 1816,485 1829,485 1920,485 1945,460 1945,425 1955,415 1995,415 2015,435 R14.2@2090,435
NetR15_1: R15.1 R23.2 U6.4 | length 418
  Layer 3 - Signal w15: v2(1975,445) 2040,445 2100,385 2185,385 v2(2220,420)
  Layer 6 - Bottom Layer w15: v2(1975,445) 1985,455 R23.2@1985,475 ; U6.4@2213.39,472.6 2213.39,441.61 2220,435 v2(2220,420) ; U6.4@2216.79,483 R15.1@2261,483
NetR20_1: R20.1 R25.2 U8.5 U8.7 | length 192.4
  Layer 6 - Bottom Layer w8: U8.7@1224.68,134.88 1224.68,115.32 1230,110 1255,110 1265,120
  Layer 6 - Bottom Layer w15: 1265,120 1280,135 1280,240
NetR26_2: R26.2 U11.12 | length 35.2
  Layer 6 - Bottom Layer w6: R26.2@300.79,150 U11.12@300.79,185.2
NetR27_2: R27.2 U11.14 | length 42.1
  Layer 6 - Bottom Layer w6: R27.2@234.96,235 239.49,230.47 U11.14@275.2,230.47
NetR29_2: R29.2 R30.2 R32.1
NetR34_2: R34.2 U13.7 U13.8
NetR39_1: R39.1 S3.2 U18.3 | length 130.3
  Layer 1 - Top Layer w8: S3.2@4348.07,460 4339.04,450.96 4350,440 v1(4375,440)
  Layer 6 - Bottom Layer w8: v1(4375,440) R39.1@4400.04,465 ; R39.1@4400.04,465 4403.19,461.85 U18.3@4403.19,424.68
NetR44_1: R44.1 U19.B1 | length 44.5
  Layer 6 - Bottom Layer w8: U19.B1@3740.53,350 R44.1@3785,350
NetR46_2: R46.2 U20.1 | length 125.4
  Layer 6 - Bottom Layer w8: U20.1@3460.12,189.53 3499.53,189.53 3525,215 R46.2@3525,265
NetR47_2: R47.2 U20.15 | length 70.7
  Layer 6 - Bottom Layer w8: U20.15@3414.84,215.12 3414.84,235 3423.84,244 3438,244 3445,251 R47.2@3445,265
NetR48_2: R48.2 U20.12 | length 37.4
  Layer 6 - Bottom Layer w8: R48.2@3312.47,189.53 U20.12@3349.88,189.53
NetR49_2: R49.2 U20.16 | length 94.6
  Layer 6 - Bottom Layer w8: U20.16@3434.53,215.12 3475.12,215.12 3485,225 R49.2@3485,265
NetR50_2: R50.2 U20.14 | length 54
  Layer 6 - Bottom Layer w8: U20.14@3395.16,215.12 3395.16,240 3405,249.84 R50.2@3405,265
NetR55_2: R55.2 U9.3 U9.4 | length 120.5
  Layer 6 - Bottom Layer w15: R55.2@2630,370 2630,400.92 U9.4@2630.71,401.63 U9.3@2719.29,401.63
NetU8_9: U8.9 U25.2 | length 109.3
  Layer 6 - Bottom Layer w8: U8.9@1185.31,134.88 1185.31,89.69 1209.69,65.31 U25.2@1239.29,65.31
PWR_DCDC1-EN: TP9.1 U10.30 U23.12 | length 986.1
  Layer 1 - Top Layer w8: v1(3243,110.79) 3289.21,110.79 3335,65 3585,65 3820,300 3900,300 3955.16,244.84 U10.30@4016.14,244.84
  Layer 6 - Bottom Layer w8: U23.12@3212.4,110.79 v1(3243,110.79) 3243,93 TP9.1@3225,75
PWR_LDO1-EN: TP10.1 U10.31 U24.4 | length 1403.2
  Layer 1 - Top Layer w8: v1(3003,248) 3112,248 3140,220 3140,85 3175,50 3595,50 3830,285 3893,285 3952.84,225.16 U10.31@4016.14,225.16
  Layer 6 - Bottom Layer w8: TP10.1@2972.74,330 2972.74,276.23 U24.4@2973.39,275.59 2994.41,275.59 3003,267 v1(3003,248)
RF430_ANT1: C49.1 C50.1 D1.2 J4.2 U14.1 | length 252.2
  Layer 1 - Top Layer w8: U14.1@5029.59,126.56 5089.56,126.56 5108,145 5108,163 5120,175 C49.1@5120,180 v1(5120,197.5) C50.1@5120,215 5120,275.35 J4.2@5119.69,275.66
  Layer 6 - Bottom Layer w8: v1(5120,197.5) 5149.04,197.5 D1.2@5150,198.46
RF430_ANT2: C49.2 C50.2 D2.2 J4.3 U14.2 | length 218.4
  Layer 1 - Top Layer w8: U14.2@5029.59,146.25 5085.25,146.25 5092,153 5092,163 5080,175 C49.2@5080,180 v1(5080,197.5) C50.2@5080,215 5080,275.35 J4.3@5080.31,275.66
  Layer 6 - Bottom Layer w8: D2.2@5055,198.46 5055.96,197.5 v1(5080,197.5)
RF430_IRQ: R64.1 U14.7 U17.8 | length 153.5
  Layer 1 - Top Layer w8: U14.7@4964.63,211.21 v1(4964.63,235)
  Layer 6 - Bottom Layer w7: U17.8@4902.56,305.75 4959.29,305.75 R64.1@4960,305.04 4964.63,300.41 v1(4964.63,235)
RF430_IRQ-V1P9: R62.1 U10.7 U17.4 | length 640.9
  Layer 1 - Top Layer w8: U10.7@4283.86,244.84 v1(4310,244.84)
  Layer 3 - Signal w7: v1(4310,244.84) 4334.84,244.84 4355,265 4400,265 4466,331 4762.96,331 v1(4782.96,351)
  Layer 6 - Bottom Layer w7: v1(4782.96,351) 4804,351 4815,340 4815,315 4824.25,305.75 U17.4@4847.44,305.75
RF430_NRES: R65.1 U14.3 U17.7 | length 453.9
  Layer 1 - Top Layer w8: U14.3@5029.59,165.93 v1(5055,165.93)
  Layer 6 - Bottom Layer w7: U17.7@4902.56,321.5 4902.56,347.56 4940,385 5005,385 5025,365 5025,310 5020.04,305.04 R65.1@5000,305.04 5000,220 5025,195 5025,175 5034.07,165.93 v1(5055,165.93)
RF430_NRES-V1P9: R63.1 U10.8 U17.5 | length 649
  Layer 1 - Top Layer w8: U10.8@4283.86,264.53 v1(4325,264.53)
  Layer 3 - Signal w7: v1@4325,265 4340,280 4390,280 4455,345 4742.96,345 v1(4782.96,385)
  Layer 6 - Bottom Layer w7: v1(4782.96,385) 4800,385 4847.44,337.56 U17.5@4847.44,321.5
RF430_SCL: R35.1 U14.10 U17.10 | length 194.8
  Layer 1 - Top Layer w8: v1(4880,175) 4882,175 4891.07,165.93 U14.10@4919.35,165.93
  Layer 6 - Bottom Layer w7: v1(4880,175) 4900,175 4910,185 4910,200 4930,220 4930,270 4925.75,274.25 U17.10@4907.56,274.25
RF430_SCL-V1P9: R37.2 U10.5 U17.2 | length 615.9
  Layer 1 - Top Layer w8: U10.5@4283.86,205.47 v1(4310,205.47)
  Layer 3 - Signal w7: v1(4310,205.47) 4335.47,205.47 4365,235 4420,235 4488,303 4762.96,303 v1(4782.96,283)
  Layer 6 - Bottom Layer w7: v1(4782.96,283) 4800,283 4808.75,274.25 U17.2@4847.44,274.25
RF430_SDA: R36.1 U14.11 U17.9 | length 269.3
  Layer 1 - Top Layer w8: v1(4879.96,135) 4881,135 4892.25,146.25 U14.11@4919.35,146.25
  Layer 6 - Bottom Layer w7: v1(4879.96,135) 4905,135 4925,155 4925,195 4945,215 4945,275 4930,290 U17.9@4907.56,290
RF430_SDA-V1P9: R38.2 U10.6 U17.3 | length 612.8
  Layer 1 - Top Layer w8: U10.6@4283.86,225.16 v1(4325,225.16)
  Layer 3 - Signal w7: v1(4325,225.16) 4335.16,225.16 4360,250 4410,250 4477,317 v1(4782.96,317)
  Layer 6 - Bottom Layer w7: v1(4782.96,317) 4786,317 4813,290 U17.3@4847.44,290
RF430_VCORE: C48.1 U10.9 U14.12 | length 1062.4
  Layer 1 - Top Layer w8: U10.9@4283.86,284.21 v1(4310,284.21)
  Layer 1 - Top Layer w15: v1(4890,65) C48.1@4919.01,65 ; C48.1@4919.35,65.34 U14.12@4919.35,123
  Layer 3 - Signal w15: v1(4310,284.21) 4294.21,284.21 4285,275 4285,180 4295,170 4330,170 4375,215 4430,215 4495,280 4750,280 4770,260 4835,260 4845,250 4845,110 v1(4890,65)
